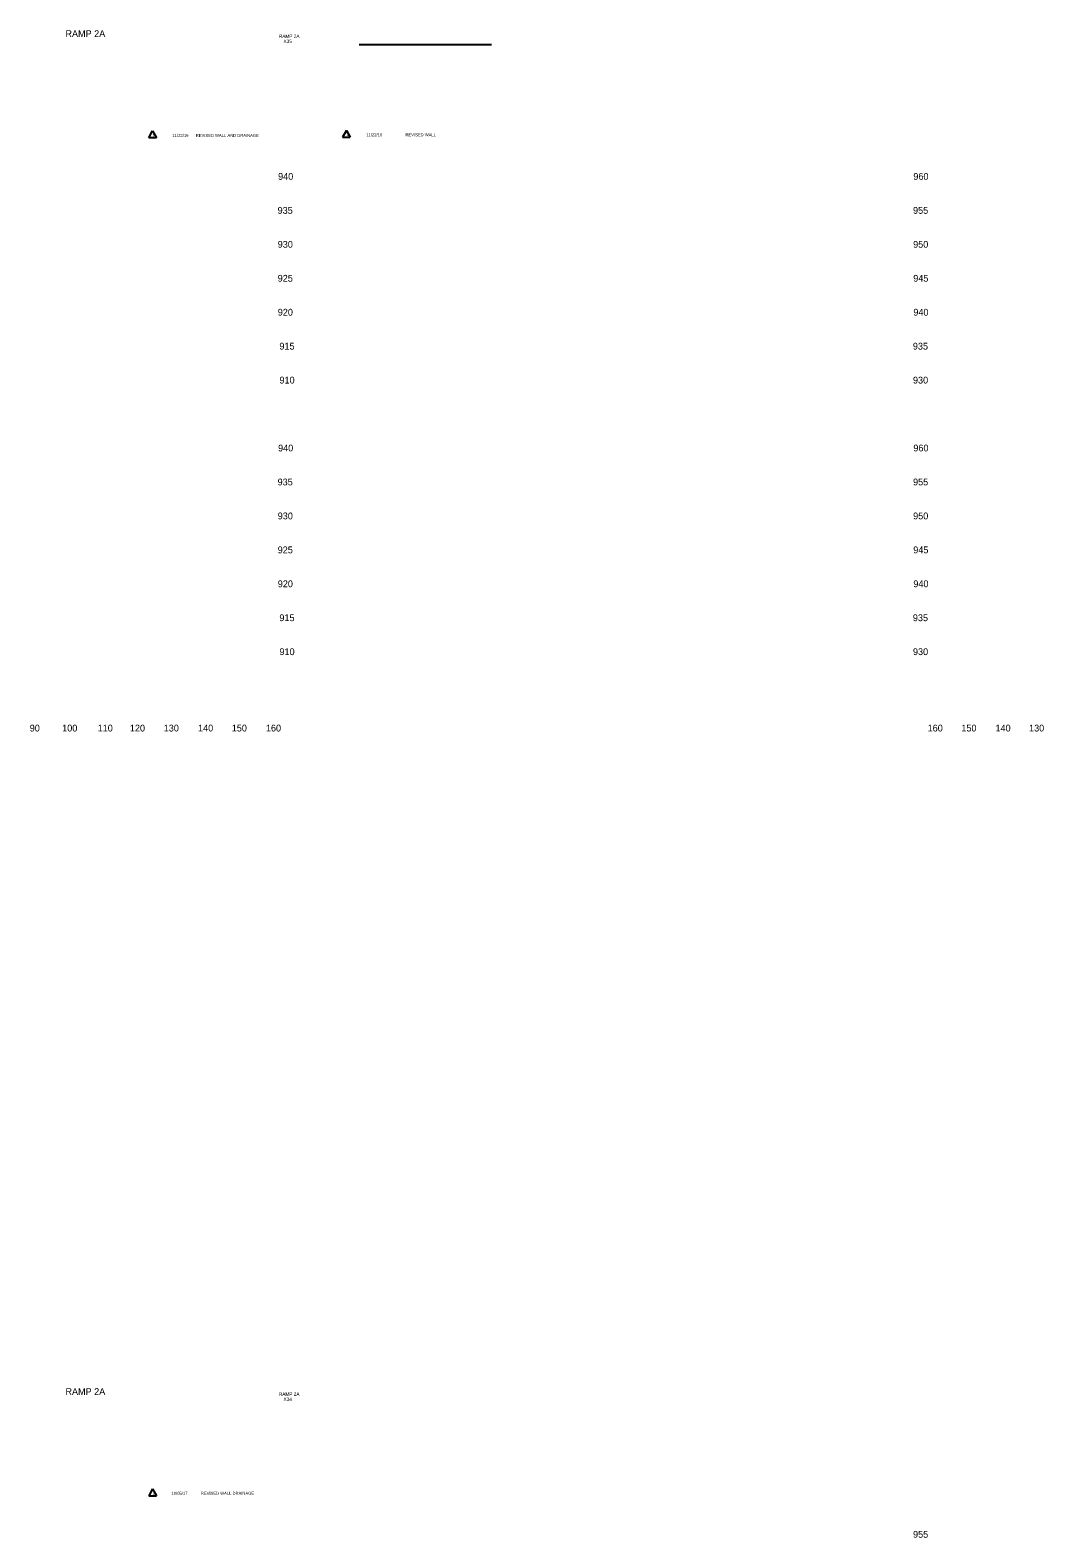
# Model space of a CAD drawing. Extents: x 4994 to 7388, y 4997 to 8804.
# Drawn here: x 6793.6 to 7092.3, y 6360 to 6804.1 of the extents above; entities that cross this region are included whole.
import ezdxf

# ---------------------------------------------------------------- set-up
doc = ezdxf.new("R2010")
doc.units = 0
for name, color, linetype in [('RD_SHT_Bndy', 7, 'Continuous'), ('RD_SHT_ID', 7, 'Continuous'), ('RD_SHT_TX', 7, 'Continuous'), ('RD_XS_TX_Offset', 7, 'Continuous')]:
    doc.layers.add(name, color=color, linetype=linetype)

msp = doc.modelspace()

# ---------------------------------------------------------------- linework, layer by layer
at = {"layer": 'RD_SHT_Bndy'}
msp.add_line((6890.61, 6799.83), (6929.61, 6799.83), dxfattribs=at)
at = {"layer": 'RD_SHT_ID'}
for p, q in [((6828.57, 6772.36), (6829.71, 6774.39)), ((6829.71, 6774.39), (6830.85, 6772.36)), ((6830.85, 6772.36), (6828.57, 6772.36))]:
    msp.add_line(p, q, dxfattribs=at)
at = {"layer": 'RD_SHT_TX'}
for p, q in [((6886.82, 6774.57), (6885.68, 6772.54)), ((6886.82, 6774.57), (6887.96, 6772.54)), ((6885.68, 6772.54), (6887.96, 6772.54)), ((6829.71, 6374.39), (6828.57, 6372.36)), ((6829.71, 6374.39), (6830.85, 6372.36)), ((6828.57, 6372.36), (6830.85, 6372.36))]:
    msp.add_line(p, q, dxfattribs=at)

# ---------------------------------------------------------------- texts
at = {"layer": 'RD_SHT_ID'}
for s, height, p in [('RAMP 2A', 2, (6804.02, 6802.06)), ('RAMP 2A', 1, (6866.93, 6801.8)), ('X35', 1, (6868.29, 6800.3)), ('RAMP 2A', 2, (6804.02, 6402.06)), ('RAMP 2A', 1, (6866.93, 6401.8)), ('X34', 1, (6868.29, 6400.3))]:
    msp.add_text(s, height=height, dxfattribs=at).set_placement(p)
at = {"layer": 'RD_SHT_TX'}
for s, p in [('1', (6829.6, 6772.59)), ('11/22/16', (6835.55, 6772.65)), ('REVISED WALL AND DRAINAGE', (6842.44, 6772.65)), ('1', (6886.82, 6772.87)), ('11/22/16', (6892.66, 6772.83)), ('REVISED WALL', (6904.23, 6772.83)), ('1', (6829.71, 6372.69)), ('10/05/17', (6835.24, 6372.65)), ('REVISED WALL DRAINAGE', (6843.96, 6372.65))]:
    msp.add_text(s, height=0.88, dxfattribs=at).set_placement(p)
at = {"layer": 'RD_XS_TX_Offset'}
for s, p in [('940', (6866.69, 6760)), ('960', (7053.89, 6760)), ('935', (6866.55, 6750)), ('955', (7053.8, 6750)), ('930', (6866.58, 6740)), ('950', (7053.83, 6740)), ('925', (6866.57, 6730)), ('945', (7053.86, 6730)), ('920', (6866.6, 6720)), ('940', (7053.89, 6720)), ('915', (6867.07, 6710)), ('935', (7053.75, 6710)), ('910', (6867.1, 6700)), ('930', (7053.78, 6700)), ('940', (6866.69, 6680)), ('960', (7053.89, 6680)), ('935', (6866.55, 6670)), ('955', (7053.8, 6670)), ('930', (6866.58, 6660)), ('950', (7053.83, 6660)), ('925', (6866.57, 6650)), ('945', (7053.86, 6650)), ('920', (6866.6, 6640)), ('940', (7053.89, 6640)), ('915', (6867.07, 6630)), ('935', (7053.75, 6630)), ('910', (6867.1, 6620)), ('930', (7053.78, 6620)), ('90', (6793.5, 6597.5)), ('100', (6803.07, 6597.5)), ('110', (6813.51, 6597.5)), ('120', (6823.01, 6597.5)), ('130', (6832.99, 6597.5)), ('140', (6843.1, 6597.5)), ('150', (6853.04, 6597.5)), ('160', (6863.1, 6597.5)), ('160', (7058.1, 6597.5)), ('150', (7068.04, 6597.5)), ('140', (7078.1, 6597.5)), ('130', (7087.99, 6597.5)), ('955', (7053.8, 6360))]:
    msp.add_text(s, height=2, dxfattribs=at).set_placement(p)

doc.saveas('drawing.dxf')
